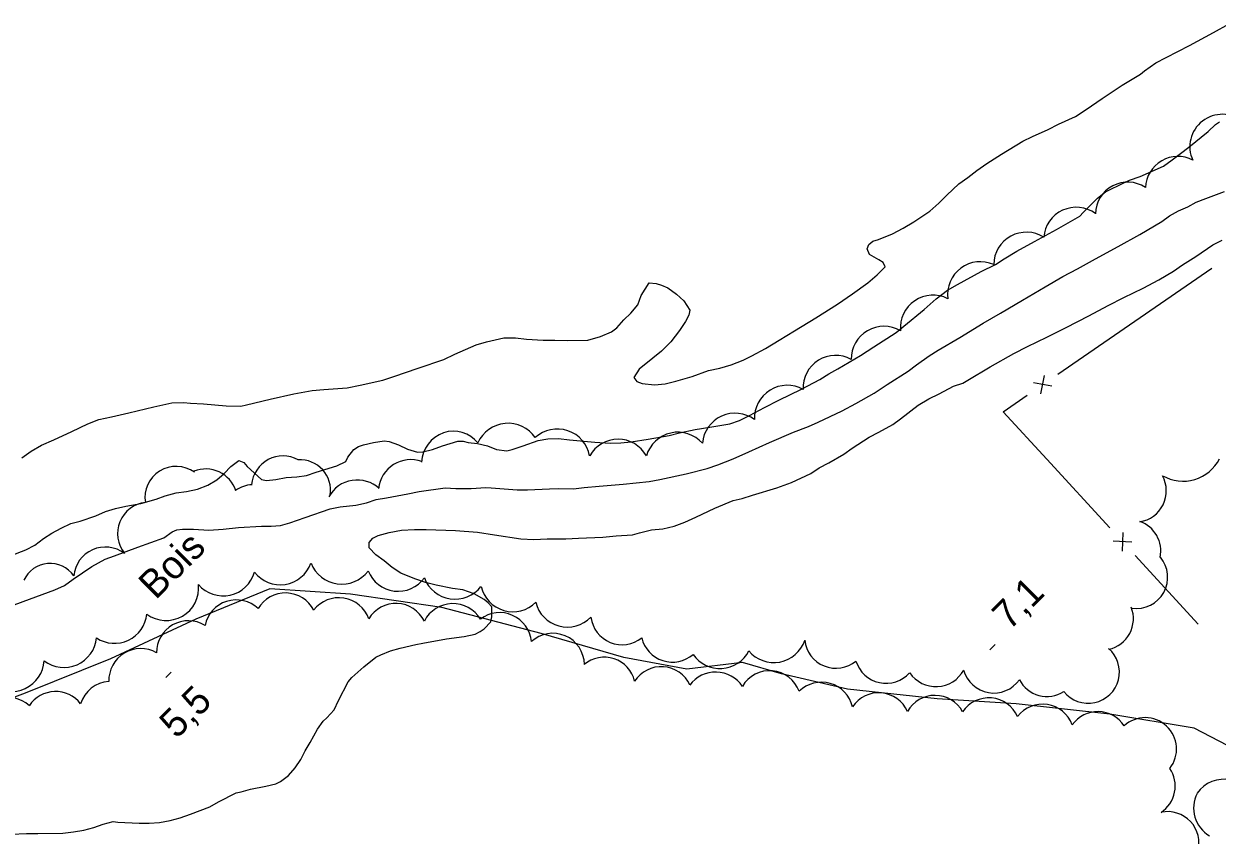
# Model space of a CAD drawing. Extents: x 381879 to 384696, y 5564785 to 5567594.
# Drawn here: x 382841.1 to 382968.9, y 5565861.6 to 5565948.5 of the extents above; entities that cross this region are included whole.
import ezdxf

# ---------------------------------------------------------------- set-up
doc = ezdxf.new("R2010")
doc.units = 0
for name, color, linetype in [('Niveau 2', 7, 'Continuous'), ('Niveau 22', 7, 'Continuous'), ('Niveau 3', 7, 'Continuous'), ('Niveau 37', 7, 'Continuous'), ('Niveau 4', 7, 'Continuous'), ('Niveau 44', 7, 'Continuous')]:
    doc.layers.add(name, color=color, linetype=linetype)

msp = doc.modelspace()

# ---------------------------------------------------------------- linework, layer by layer
at = {"layer": 'Niveau 2'}
for points in [[(382856.27, 5565897.9), (382857.42, 5565898.22), (382858.52, 5565898.37), (382859.7, 5565898.64), (382860.82, 5565899.06), (382861.77, 5565899.64), (382862.58, 5565900.31), (382863.3, 5565901.07), (382864.16, 5565901.7), (382864.67, 5565901.49), (382865.05, 5565901.07), (382866.56, 5565899.65), (382867.09, 5565899.55), (382868.11, 5565899.65), (382869.22, 5565899.86), (382870.34, 5565899.93), (382871.39, 5565900.1), (382872.43, 5565900.45), (382874.65, 5565901.14), (382875.61, 5565901.58), (382875.83, 5565902.05), (382876.46, 5565902.89), (382876.95, 5565903.18), (382877.49, 5565903.36), (382878.58, 5565903.64), (382879.7, 5565903.79), (382880.26, 5565903.73), (382881.25, 5565903.37), (382882.22, 5565902.92), (382883.28, 5565902.58), (382883.86, 5565902.61), (382884.87, 5565902.86), (382885.94, 5565903.25), (382887.6, 5565903.75), (382888.18, 5565903.75), (382888.72, 5565903.64), (382889.72, 5565903.53), (382890.76, 5565903.26), (382891.73, 5565902.86), (382892.83, 5565902.74), (382893.4, 5565902.87), (382894.6, 5565903.26), (382896.2, 5565903.83), (382897.23, 5565904.03), (382898.39, 5565904.04), (382899.54, 5565903.92), (382902.28, 5565903.67), (382903.92, 5565903.57), (382905.07, 5565903.59), (382906.15, 5565903.7), (382907.98, 5565903.98), (382910.24, 5565904.39), (382911.32, 5565904.67), (382913.03, 5565905.03), (382914.57, 5565905.25), (382916.72, 5565905.63), (382917.76, 5565905.99), (382918.83, 5565906.5), (382920.45, 5565907.38), (382921.99, 5565908.15), (382924.39, 5565909.34), (382926.35, 5565910.37), (382927.32, 5565910.99), (382928.31, 5565911.53), (382930.73, 5565912.93), (382932.16, 5565913.88), (382934.53, 5565915.42), (382935.35, 5565916.09), (382937.53, 5565917.87), (382938.81, 5565919.01), (382940.04, 5565919.94), (382941.11, 5565920.55), (382943.64, 5565921.95), (382945.17, 5565922.69), (382946.09, 5565923.3), (382947.48, 5565924.12), (382949.37, 5565925.15), (382951.71, 5565926.44), (382954.21, 5565927.88), (382954.56, 5565928.25), (382956.1, 5565929.8), (382956.96, 5565930.47), (382957.45, 5565930.72), (382959.53, 5565931.71), (382960.66, 5565932.12), (382963.16, 5565933.21), (382964.11, 5565933.89), (382965.87, 5565935.26), (382967.97, 5565936.95), (382968.74, 5565937.69), (382969.17, 5565937.95)], [(382883.44, 5565898.37), (382886.24, 5565898.76), (382887.37, 5565898.71), (382889.03, 5565898.71), (382890.59, 5565898.82), (382891.18, 5565898.76), (382893.96, 5565898.56), (382895.04, 5565898.56), (382897.4, 5565898.68), (382898.41, 5565898.69), (382899.97, 5565898.65), (382901.11, 5565898.81), (382902.72, 5565898.94), (382905.3, 5565899.15), (382908.1, 5565899.44), (382909.23, 5565899.67), (382912.06, 5565900.28), (382914.29, 5565900.85), (382915.43, 5565901.25), (382917.07, 5565901.88), (382918.76, 5565902.61), (382920.96, 5565903.62), (382923.53, 5565904.73), (382925.16, 5565905.33), (382926.2, 5565905.79), (382928.75, 5565907.01), (382930.21, 5565907.8), (382932.19, 5565908.92), (382933.59, 5565909.82), (382935.82, 5565911.28), (382936.72, 5565911.96), (382938.08, 5565912.92), (382939.04, 5565913.5), (382941.37, 5565914.87), (382943.87, 5565916.4), (382945.7, 5565917.47), (382948.08, 5565918.88), (382950.48, 5565920.31), (382952.39, 5565921.39), (382953.96, 5565922.22), (382955.88, 5565923.3), (382958.32, 5565924.63), (382960.65, 5565925.9), (382962.99, 5565927.3), (382963.83, 5565927.9), (382964.79, 5565928.45), (382965.77, 5565928.88), (382966.66, 5565929.37), (382967.71, 5565929.75), (382969.69, 5565930.51)], [(382883.85, 5565882.15), (382886.38, 5565882.61), (382888.29, 5565882.85), (382889.45, 5565883.11), (382890, 5565883.37), (382890.41, 5565883.67), (382891.13, 5565884.43), (382891.25, 5565884.95), (382891.23, 5565886.03), (382890.85, 5565886.47), (382890.42, 5565886.82), (382889.35, 5565887.42), (382888.14, 5565887.85), (382887.04, 5565887.98), (382885.27, 5565888.33), (382884.12, 5565888.63), (382883, 5565889.01), (382881.49, 5565889.64), (382880.55, 5565890.25), (382879.72, 5565890.95), (382878.83, 5565891.59), (382878.1, 5565892.33), (382878.11, 5565892.9), (382878.49, 5565893.38), (382879.07, 5565893.65), (382880.23, 5565893.97), (382881.57, 5565894.23), (382882.96, 5565894.32), (382884.21, 5565894.3), (382887.35, 5565894.21), (382889.71, 5565894.02), (382891.53, 5565893.75), (382894.35, 5565893.3), (382895.73, 5565893.25), (382897.18, 5565893.29), (382899.16, 5565893.3), (382900.51, 5565893.37), (382903.12, 5565893.5), (382904.54, 5565893.63), (382906.31, 5565893.72), (382907.04, 5565893.96), (382908.33, 5565894.26), (382909.55, 5565894.38), (382910.78, 5565894.68), (382911.91, 5565895.1), (382913.09, 5565895.62), (382915.13, 5565896.58), (382917.07, 5565897.4), (382918.06, 5565897.63), (382919.14, 5565897.97), (382921.76, 5565898.77), (382923.34, 5565899.35), (382925.41, 5565900.29), (382926.3, 5565900.92), (382927.32, 5565901.45), (382928.94, 5565902.37), (382929.84, 5565903), (382931.64, 5565904.19), (382932.68, 5565904.72), (382934.2, 5565905.56), (382935.02, 5565906.17), (382936.9, 5565907.62), (382938.03, 5565908.3), (382939.16, 5565908.83), (382940.69, 5565909.65), (382941.67, 5565909.97), (382942.23, 5565910.3), (382944.61, 5565911.73), (382947.14, 5565913.17), (382948.61, 5565913.91), (382950.66, 5565914.89), (382952.76, 5565915.95), (382955.18, 5565917.2), (382957.25, 5565918.31), (382958.91, 5565919.14), (382961.01, 5565920.15), (382962.66, 5565921.05), (382964.25, 5565921.98), (382965.2, 5565922.64), (382966.62, 5565923.53), (382968.47, 5565924.79), (382969.47, 5565925.31)], [(382839.75, 5565891.53), (382841.32, 5565892.14), (382842.28, 5565892.63), (382843.22, 5565893.35), (382844.12, 5565893.93), (382845.1, 5565894.46), (382846.14, 5565894.94), (382847.15, 5565895.21), (382848.81, 5565895.77), (382849.87, 5565896.24), (382850.95, 5565896.56), (382852.03, 5565896.8), (382853.63, 5565897.1), (382855.3, 5565897.55), (382856.27, 5565897.9)], [(382853.34, 5565892.41), (382856.1, 5565893.42), (382857.02, 5565894.04), (382857.51, 5565894.26), (382858.1, 5565894.36), (382859.27, 5565894.34), (382860.94, 5565894.25), (382862.47, 5565894.34), (382864.1, 5565894.51), (382866.58, 5565894.68), (382867.6, 5565894.66), (382868.62, 5565894.72), (382869.62, 5565895.01), (382871.25, 5565895.6), (382873.91, 5565896.52), (382874.98, 5565896.72), (382876.69, 5565896.91), (382877.82, 5565897.17), (382878.85, 5565897.51), (382879.94, 5565897.69), (382882.24, 5565898.13), (382883.44, 5565898.37)], [(382816.69, 5565880.53), (382817.81, 5565880.66), (382819.42, 5565880.7), (382821.1, 5565880.89), (382823.29, 5565881.22), (382824.34, 5565881.59), (382825.97, 5565882.04), (382827.53, 5565882.39), (382829.14, 5565882.69), (382831.36, 5565883.15), (382832.44, 5565883.5), (382834.04, 5565883.96), (382835.6, 5565884.53), (382838.1, 5565885.45), (382840.08, 5565886.25), (382841.74, 5565886.86), (382844.42, 5565887.85), (382845.46, 5565888.31), (382846.4, 5565888.98), (382848.4, 5565890.36), (382849.81, 5565891.12), (382850.84, 5565891.5), (382853.31, 5565892.4), (382853.34, 5565892.41)], [(382839.78, 5565861.66), (382841.4, 5565861.75), (382842.61, 5565861.74), (382845.28, 5565861.8), (382846.44, 5565861.91), (382847.54, 5565862.09), (382848.63, 5565862.39), (382849.63, 5565862.75), (382850.67, 5565863.03), (382851.19, 5565862.98), (382853.46, 5565862.84), (382854.53, 5565862.85), (382855.65, 5565862.92), (382856.78, 5565863.14), (382857.86, 5565863.43), (382858.95, 5565863.82), (382861.04, 5565864.61), (382861.97, 5565865.13), (382863.86, 5565866.12), (382864.41, 5565866.22), (382865.4, 5565866.48), (382867.03, 5565866.82), (382868.12, 5565867.07), (382868.61, 5565867.33), (382869.46, 5565867.97), (382870.19, 5565868.77), (382870.78, 5565869.66), (382871.24, 5565870.59), (382871.78, 5565871.5), (382872.56, 5565872.92), (382873.16, 5565873.79), (382873.57, 5565874.14), (382874.34, 5565874.99), (382874.82, 5565876.01), (382875.84, 5565878), (382876.25, 5565878.45), (382877.52, 5565879.6), (382878.81, 5565880.65), (382879.34, 5565880.9), (382880.37, 5565881.3), (382881.41, 5565881.59), (382883.11, 5565881.99), (382883.85, 5565882.15)]]:
    msp.add_lwpolyline(points, dxfattribs=at)
at = {"layer": 'Niveau 22'}
msp.add_lwpolyline([(382987.43, 5565867.35), (382981.58, 5565866.53), (382973.58, 5565869.32), (382966.46, 5565873.03), (382957.42, 5565874.52), (382947.4, 5565875.65), (382938.92, 5565876.16), (382929.33, 5565877.22), (382922.27, 5565878.85), (382918.08, 5565880.07), (382912.12, 5565879.35), (382905.38, 5565880.6), (382896.51, 5565883.17), (382885.87, 5565885.97), (382876.11, 5565887.38), (382867.47, 5565887.96), (382859.53, 5565884.71), (382850.41, 5565880.45), (382841.25, 5565876.77), (382830.1, 5565872.61)], dxfattribs=at)
at = {"layer": 'Niveau 3'}
for p, q in [((382944.58, 5565881.43), (382945.15, 5565882)), ((382856.31, 5565878.47), (382856.88, 5565879.04))]:
    msp.add_line(p, q, dxfattribs=at)
at = {"layer": 'Niveau 37'}
for p, q in [((382950.05, 5565908.84), (382950.41, 5565910.81)), ((382951.21, 5565909.64), (382949.24, 5565910.01)), ((382958.81, 5565894), (382958.73, 5565892)), ((382959.77, 5565892.96), (382957.77, 5565893.05))]:
    msp.add_line(p, q, dxfattribs=at)
for points in [[(382960.11, 5565916.63), (382968.34, 5565922.3)], [(382951.87, 5565910.96), (382960.11, 5565916.63)], [(382950.66, 5565901.85), (382946.01, 5565906.92), (382948.58, 5565908.69)], [(382957.42, 5565894.48), (382950.66, 5565901.85)], [(382966.88, 5565884.16), (382960.12, 5565891.53)]]:
    msp.add_lwpolyline(points, dxfattribs=at)
at = {"layer": 'Niveau 4'}
for points in [[(382944.26, 5565933.52), (382945.81, 5565934.49), (382948.1, 5565935.9), (382949.14, 5565936.4), (382950.81, 5565937.13), (382951.94, 5565937.7), (382953.73, 5565938.54), (382954.89, 5565939.28), (382956.61, 5565940.47), (382958.75, 5565941.88), (382960.7, 5565943.08), (382961.12, 5565943.43), (382962.36, 5565944.27), (382963.46, 5565944.86), (382965.95, 5565946.15), (382968.54, 5565947.52), (382970.19, 5565948.46)], [(382840.89, 5565901.97), (382841.91, 5565902.68), (382843.01, 5565903.35), (382844.33, 5565903.91), (382846.25, 5565904.79), (382847.96, 5565905.64), (382849.15, 5565906.09), (382850.52, 5565906.36), (382852.37, 5565906.81), (382855.03, 5565907.46), (382856.95, 5565907.86), (382858.23, 5565907.92), (382858.96, 5565907.84), (382860.37, 5565907.76), (382862.8, 5565907.54), (382864.36, 5565907.5), (382864.96, 5565907.65), (382867.51, 5565908.26), (382870.05, 5565908.82), (382872.01, 5565909.2), (382873.25, 5565909.29), (382875.76, 5565909.49), (382877.15, 5565909.75), (382879.57, 5565910.29), (382880.75, 5565910.71), (382883.34, 5565911.59), (382886.09, 5565912.52), (382887.28, 5565913.09), (382889.55, 5565914.09), (382890.65, 5565914.4), (382892.53, 5565914.84), (382893.78, 5565914.85), (382894.96, 5565914.69), (382896.72, 5565914.58), (382897.97, 5565914.59), (382899.3, 5565914.54), (382901.51, 5565914.58), (382902.88, 5565914.98), (382904.05, 5565915.49), (382904.61, 5565915.91), (382905.38, 5565916.76), (382906.14, 5565917.47), (382906.88, 5565918.38), (382907.24, 5565919.37), (382908.09, 5565920.71), (382908.84, 5565920.65), (382909.4, 5565920.49), (382910.07, 5565920.18), (382911.02, 5565919.52), (382911.81, 5565918.8), (382912.43, 5565917.78), (382912.33, 5565917.27), (382911.99, 5565916.59), (382911.32, 5565915.62), (382910.4, 5565914.41), (382909.42, 5565913.41), (382908.49, 5565912.64), (382907.01, 5565911.49), (382906.44, 5565910.58), (382906.75, 5565910.16), (382907.34, 5565909.94), (382908.66, 5565909.79), (382909.81, 5565909.9), (382910.95, 5565910.18), (382912.71, 5565910.7), (382914.43, 5565911.32), (382915.65, 5565911.59), (382916.86, 5565911.95), (382918.14, 5565912.43), (382919.09, 5565912.89), (382920.54, 5565913.69), (382922, 5565914.6), (382923.64, 5565915.57), (382925.95, 5565916.97), (382928.25, 5565918.45), (382929.85, 5565919.53), (382931.51, 5565920.73), (382932.5, 5565921.59), (382933.35, 5565922.43), (382933.16, 5565922.9), (382932.68, 5565923.18), (382931.67, 5565923.75), (382931.44, 5565924.35), (382931.6, 5565924.83), (382932.05, 5565925.18), (382932.64, 5565925.38), (382934.14, 5565925.97), (382935.28, 5565926.58), (382936.44, 5565927.27), (382938.13, 5565928.4), (382939.11, 5565929.24), (382939.97, 5565930.1), (382941.25, 5565931.31), (382942.2, 5565931.99), (382943.17, 5565932.77), (382944.26, 5565933.52)]]:
    msp.add_lwpolyline(points, dxfattribs=at)
at = {"layer": 'Niveau 44'}
for centre, radius, start, end in [((382943.55, 5565919.48), 3.51, 65.8867, 187.5163), ((382917.28, 5565903.26), 3.5, 53.4168, 175.1924), ((382965.26, 5565903.85), 4.37, 240.008, 333.2149), ((382868.57, 5565891.9), 3.51, 218.1454, 339.8581), ((382845.41, 5565883.03), 3.5, 232.7574, 354.5013), ((382915.66, 5565882.92), 3.5, 214.7677, 332.5856), ((382839.77, 5565880.48), 3.53, 234.4078, 356.143), ((382926.54, 5565874.56), 3.4, 12.8684, 134.7113), ((382839.39, 5565872.85), 3.48, 48.0606, 170.1195), ((382932.67, 5565873.44), 3.38, 24.083, 146.229), ((382969.64, 5565864.07), 3.49, 78.0146, 145.4086), ((382969.9, 5565864.49), 3.5, 153.542, 239.218)]:
    msp.add_arc(centre, radius, start, end, dxfattribs=at)
for centre, major_axis, ratio, start_param, end_param in [((382969.45, 5565935.32), (-2.92, -1.87), 0.993517, 3.449721, 6.148784), ((382964.7, 5565930.8), (-3.13, -1.52), 0.992677, 3.777472, 5.787549), ((382959.35, 5565928.03), (-1.64, 3.07), 0.99736, 5.217323, 7.336096), ((382953.82, 5565925.33), (-1.03, 3.33), 0.999768, 5.349701, 7.475257), ((382948.48, 5565922.65), (-1.68, 3.07), 0.998952, 5.216114, 7.34455), ((382938.49, 5565915.9), (-0.92, 3.38), 0.999963, 5.54849, 7.673907), ((382933.23, 5565912.58), (-1.6, 3.11), 0.998872, 5.275461, 7.399249), ((382928.06, 5565909.45), (-1.9, 2.95), 0.992633, 5.21051, 7.324697), ((382922.88, 5565906.24), (-1.65, 3.1), 0.999167, 5.287123, 7.411695), ((382892.97, 5565902.14), (-0.22, 3.54), 0.996864, 5.250432, 7.373653), ((382887.09, 5565901.37), (-1.21, -3.26), 0.973399, 2.609357, 5.014382), ((382898.26, 5565901.55), (1.12, 3.33), 0.999868, 5.220212, 7.347597), ((382911.17, 5565901.21), (-0.78, 3.43), 0.99981, 5.217903, 7.345369), ((382904.76, 5565900.49), (-0.03, 3.49), 0.996066, 5.216574, 7.336339), ((382868.84, 5565898.87), (-2.82, -1.81), 0.988261, 3.63415, 5.632887), ((382870.52, 5565898.41), (3.12, 1.53), 0.964124, 5.695749, 7.421136), ((382882.54, 5565898.34), (-2.95, -1.82), 0.992702, 3.812698, 5.624286), ((382857.44, 5565897.76), (-3.35, -0.07), 0.984822, 4.072018, 6.429581), ((382860.63, 5565897.46), (-3.13, 1.23), 0.987912, 3.824256, 5.477412), ((382865.71, 5565895.79), (-3.19, -1.04), 0.988392, 4.446723, 5.009146), ((382876.8, 5565896.17), (-3.03, -1.67), 0.992743, 3.452636, 5.281949), ((382960.13, 5565898.45), (1.83, 2.8), 0.999598, 3.869676, 5.790482), ((382854.55, 5565893.85), (-3.15, 1.27), 0.995534, 5.213442, 7.336515), ((382959.53, 5565892), (-1.37, 3.06), 0.999984, 4.087093, 5.52727), ((382849.85, 5565889.03), (-1.39, 3.1), 0.999185, 5.21643, 7.342531), ((382843.93, 5565887.6), (-0.29, 3.07), 0.996016, 5.217519, 7.337685), ((382875.16, 5565891.99), (-0.46, -3.51), 0.997688, 5.218501, 7.338217), ((382960.27, 5565889.2), (1.97, 2.71), 0.999598, 3.633473, 6.036037), ((382862.46, 5565890.68), (3.4, 0.75), 0.998796, 3.634384, 5.790394), ((382881.21, 5565891.17), (-0.6, -3.43), 0.998702, 5.269785, 7.396942), ((382887.3, 5565890.34), (-0.52, -3.46), 0.999952, 5.219412, 7.349101), ((382856.36, 5565888.04), (2.88, 1.96), 0.998802, 3.480539, 5.791908), ((382893.49, 5565888.99), (-0.96, -3.36), 0.998952, 5.216468, 7.34348), ((382863.87, 5565883.35), (-1.03, 3.26), 0.999978, 5.223891, 7.346069), ((382869.14, 5565884.11), (0.1, 3.4), 0.999909, 5.219941, 7.349698), ((382874.85, 5565883.57), (1.05, 3.26), 0.999827, 5.376004, 7.499663), ((382880.97, 5565882.98), (-1.8, -2.89), 0.999983, 2.59048, 4.722405), ((382887.07, 5565882.93), (0.52, 3.4), 0.999884, 5.406194, 7.530399), ((382899.34, 5565887.35), (-1.08, -3.33), 0.998361, 5.266375, 7.394679), ((382850.81, 5565885.63), (1.63, -3.11), 0.99974, 5.222468, 7.262582), ((382892.08, 5565881.98), (1.61, 3.02), 0.999254, 5.295096, 7.420373), ((382956.6, 5565884.76), (1.58, -2.96), 0.996926, 6.003426, 7.73696), ((382858.75, 5565881.11), (-1.59, 3.04), 0.997413, 5.256146, 7.380877), ((382905.2, 5565885.35), (-1.34, -3.11), 0.995334, 5.246965, 7.361974), ((382897.76, 5565879.8), (2.44, 2.36), 0.999149, 5.531208, 7.825171), ((382910.58, 5565883.48), (-0.91, -3.25), 0.999948, 5.218633, 7.271438), ((382853.63, 5565878.14), (0.09, -3.41), 0.999983, 2.591292, 4.720989), ((382921.45, 5565883.54), (0.63, -3.43), 0.999865, 5.223337, 7.347517), ((382928.09, 5565882.8), (-2.52, -2.21), 0.999131, 5.670194, 7.825493), ((382955.1, 5565879.04), (3.35, -0.09), 0.999081, 3.842081, 7.169823), ((382903.27, 5565877.27), (0.99, 3.21), 0.998534, 5.251459, 7.271698), ((382933.46, 5565881.2), (-1.48, -3.03), 0.999925, 5.460831, 7.583428), ((382909.38, 5565876.21), (0.34, 3.39), 0.997134, 5.252107, 7.3771), ((382915.2, 5565875.56), (1.28, 3.23), 0.99993, 5.684798, 7.585628), ((382920.99, 5565875.82), (-2.09, -2.64), 0.999983, 2.5905, 4.858802), ((382938.8, 5565880.85), (2.75, 1.96), 0.999994, 3.114776, 5.172338), ((382945, 5565880.16), (-0.34, -3.35), 0.997908, 5.089723, 7.336756), ((382850.43, 5565874.64), (-1.41, -3.08), 0.999859, 3.634248, 4.840675), ((382950.7, 5565879.78), (3.22, 0.92), 0.999712, 3.349134, 4.995), ((382844.53, 5565873.57), (-3.37, 0.32), 0.999749, 3.897167, 5.791852), ((382938.7, 5565873.16), (0.02, 3.38), 0.99903, 5.221408, 7.346319), ((382944.46, 5565872.89), (0.43, 3.36), 0.997828, 5.260953, 7.386282), ((382950.23, 5565872.22), (0.51, 3.34), 0.999994, 5.218761, 7.350514), ((382956.14, 5565871.45), (-3.33, 0.41), 0.999984, 3.841958, 5.790452), ((382961.21, 5565870.8), (-2.73, 1.95), 0.999984, 3.091463, 6.074031), ((382961.06, 5565866.82), (0.54, 3.32), 0.999857, 3.884586, 5.473587), ((382963.61, 5565860.74), (-2.71, 1.98), 0.999984, 3.496697, 5.554033)]:
    msp.add_ellipse(centre, major_axis=major_axis, ratio=ratio, start_param=start_param, end_param=end_param, dxfattribs=at)

# ---------------------------------------------------------------- texts
at = {"layer": 'Niveau 3'}
for s, p in [('7,1  ', (382946.65, 5565883.43)), ('5,5  ', (382857.47, 5565871.8))]:
    msp.add_text(s, height=3, rotation=44.7717, dxfattribs=at).set_placement(p)
at = {"layer": 'Niveau 44'}
msp.add_text('Bois', height=3, rotation=44.7707, dxfattribs=at).set_placement((382855.23, 5565886.71))

doc.saveas('drawing.dxf')
